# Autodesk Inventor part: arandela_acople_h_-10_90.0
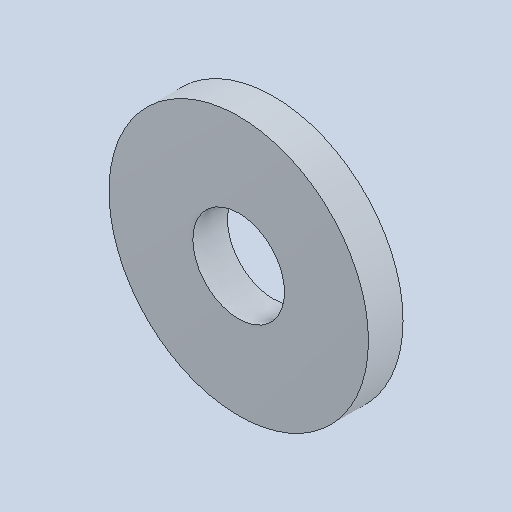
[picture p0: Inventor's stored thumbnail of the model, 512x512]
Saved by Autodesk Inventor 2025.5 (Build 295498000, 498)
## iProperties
Created: 2026-10
Part Number: arandela_acople_h_-10_90.0
Material: Genérico
Document SubType Name: Modeling
Designer: Luis M
Density: 1 g/cm^3
Appearance: Valor por defecto
Author: Luis M
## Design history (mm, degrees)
feature "Base1"
node "Sólido1"
